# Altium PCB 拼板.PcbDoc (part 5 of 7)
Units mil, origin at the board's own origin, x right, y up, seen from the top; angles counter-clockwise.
Board outline 3630.03 x 5330.03 mil, 2 copper layers (Top Layer, Bottom Layer); 416 components, 35 nets, 1936 pads, 800 vias.
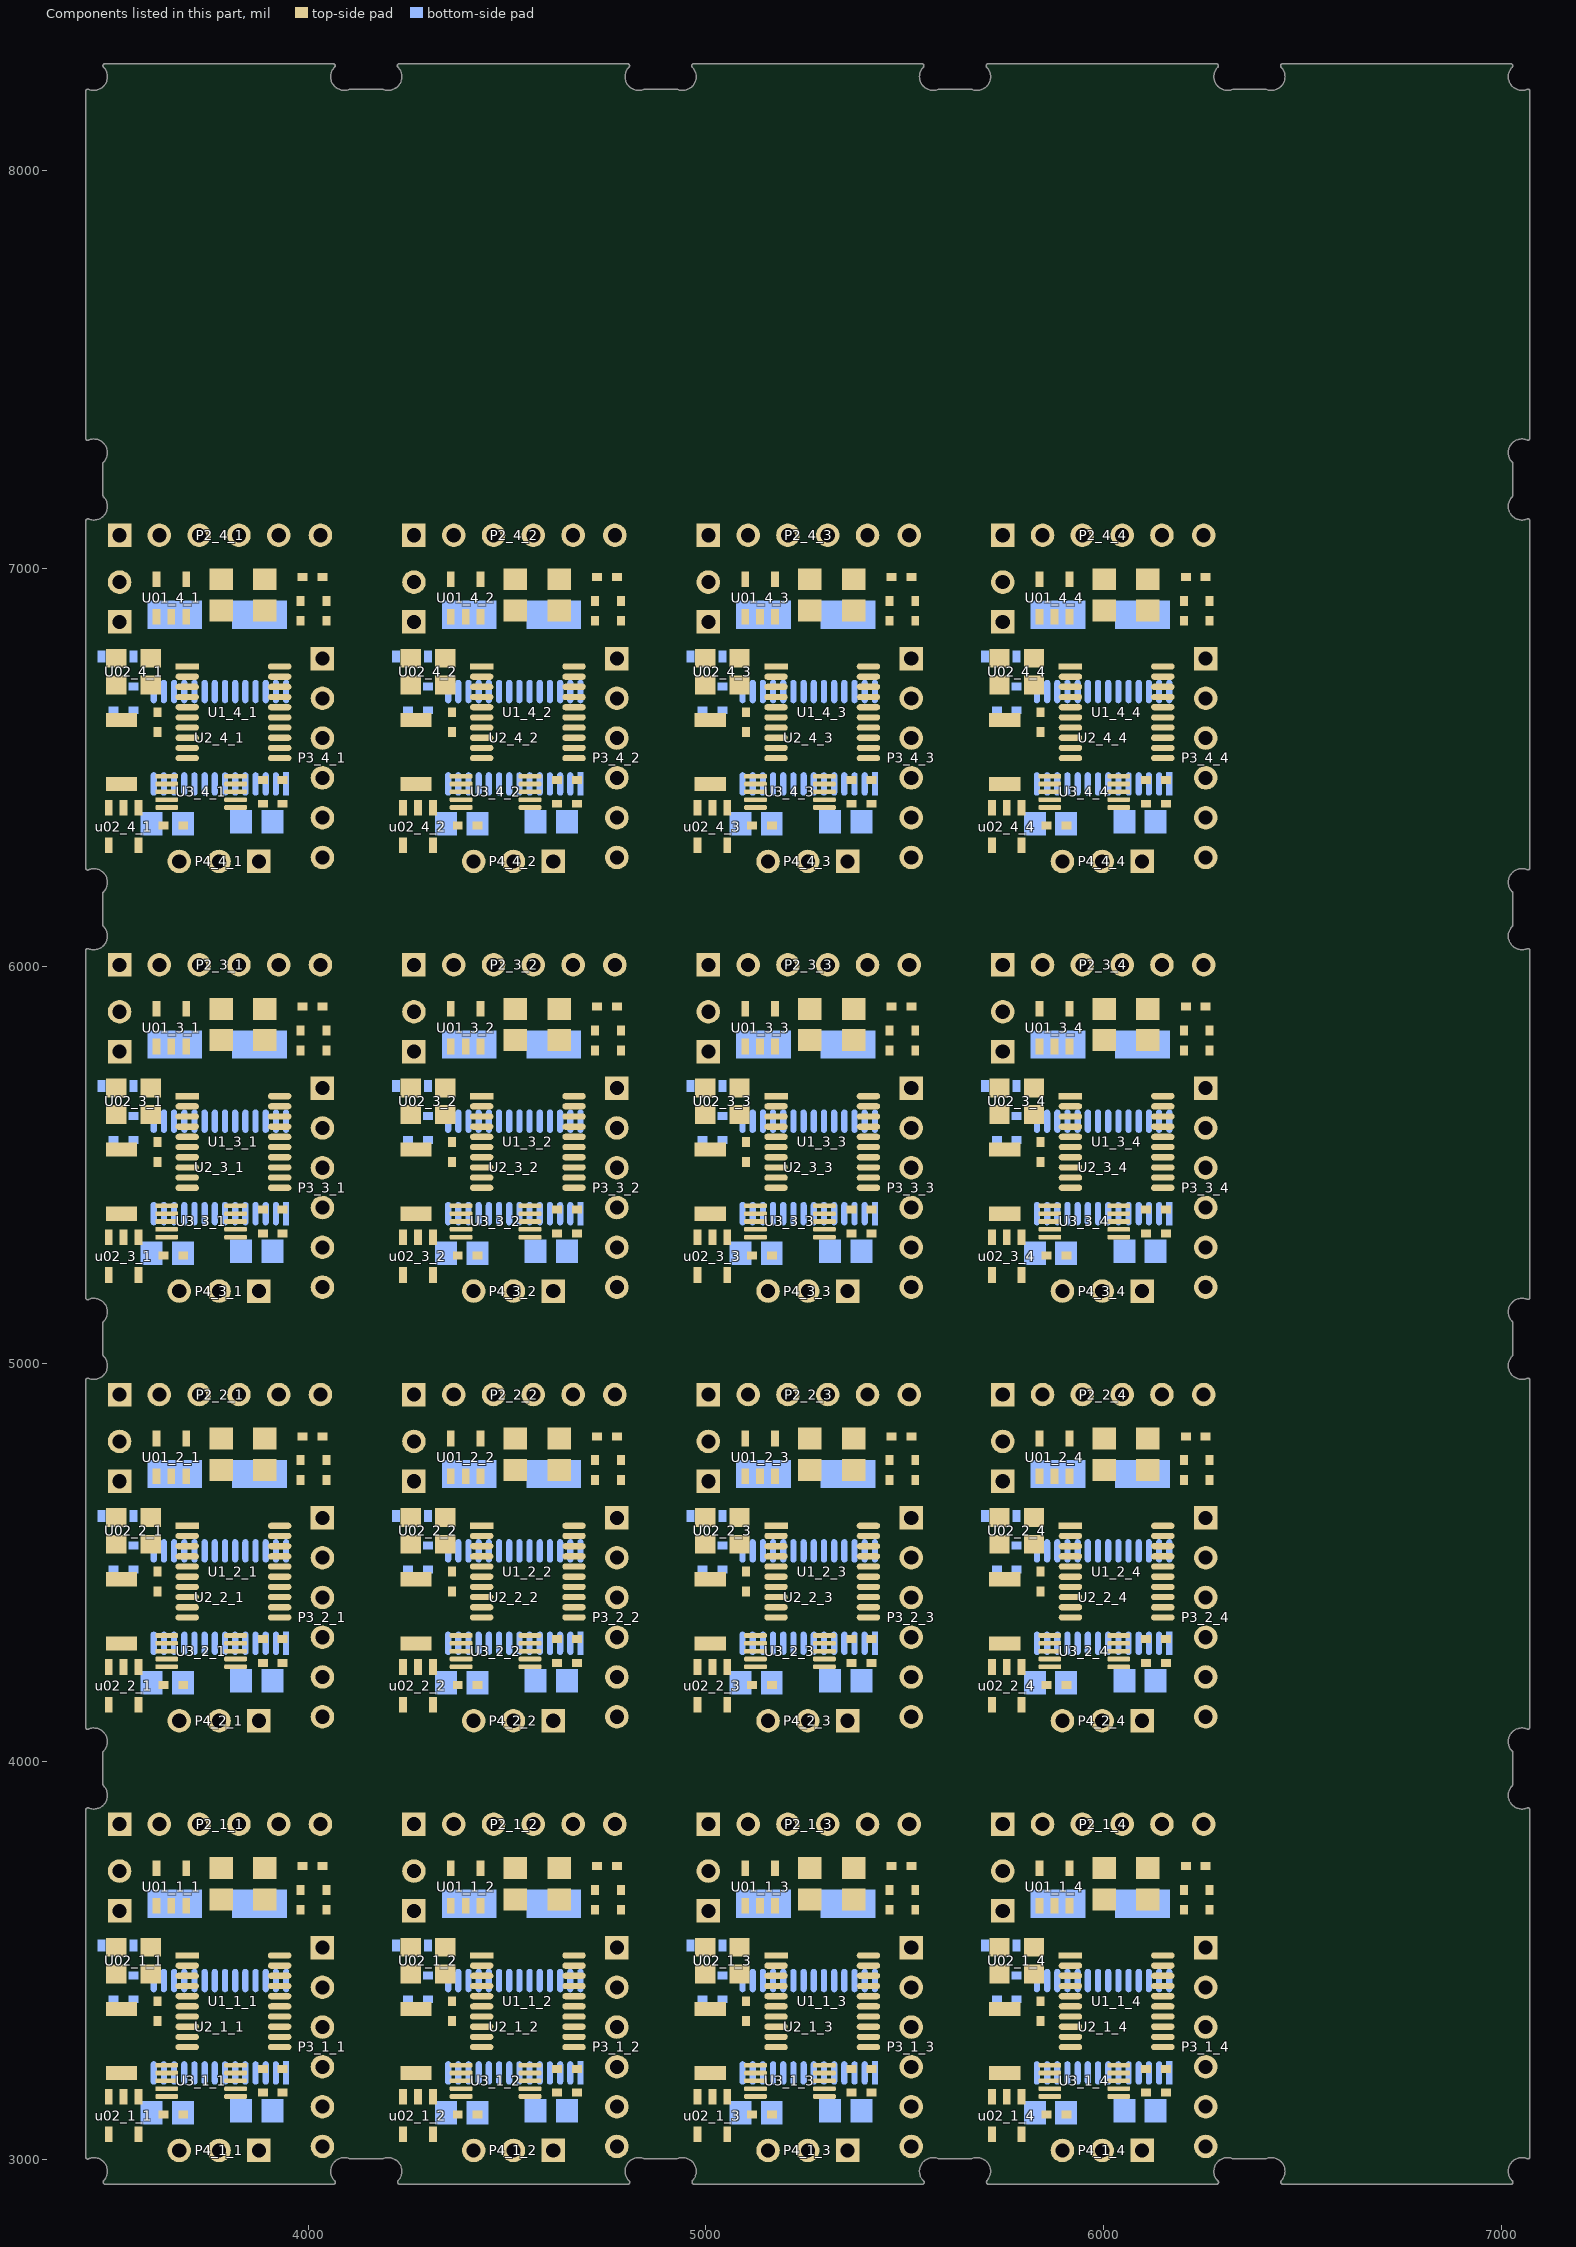
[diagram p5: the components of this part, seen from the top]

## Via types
v1: diameter 24, hole 24, Top Layer to Bottom Layer, 480 vias
v2: diameter 20, hole 10, Top Layer to Bottom Layer, 240 vias
v3: diameter 36, hole 20, Top Layer to Bottom Layer, 48 vias
v4: diameter 32, hole 16, Top Layer to Bottom Layer, 32 vias

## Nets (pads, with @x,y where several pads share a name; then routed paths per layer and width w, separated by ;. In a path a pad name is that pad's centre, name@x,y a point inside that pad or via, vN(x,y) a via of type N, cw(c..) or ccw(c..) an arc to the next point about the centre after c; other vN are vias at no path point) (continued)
copper on no net: (continued)
  Bottom Layer w8: 3511.07,3403.02 3513.57,3403.02 3519.57,3409.02 3519.57,3424.02 3558.57,3463.02 3561.07,3463.02 3608.35,3463.02 3611.93,3459.44 3611.93,3450.02 ; 3511.07,4483.02 3513.57,4483.02 3519.57,4489.02 3519.57,4504.02 3558.57,4543.02 3561.07,4543.02 3608.35,4543.02 3611.93,4539.44 3611.93,4530.02 ; 3511.07,5563.02 3513.57,5563.02 3519.57,5569.02 3519.57,5584.02 3558.57,5623.02 3561.07,5623.02 3608.35,5623.02 3611.93,5619.44 3611.93,5610.02 ; 3511.07,6643.02 3513.57,6643.02 3519.57,6649.02 3519.57,6664.02 3558.57,6703.02 3561.07,6703.02 3608.35,6703.02 3611.93,6699.44 3611.93,6690.02 ; 3561.07,3403.02 3608.18,3403.02 3723.18,3288.02 v2(3756.07,3288.02) 3756.07,3318.02 3688.7,3385.38 3688.7,3450.02 ; 3561.07,4483.02 3608.18,4483.02 3723.18,4368.02 v2(3756.07,4368.02) 3756.07,4398.02 3688.7,4465.38 3688.7,4530.02 ; 3561.07,5563.02 3608.18,5563.02 3723.18,5448.02 v2(3756.07,5448.02) 3756.07,5478.02 3688.7,5545.38 3688.7,5610.02 ; 3561.07,6643.02 3608.18,6643.02 3723.18,6528.02 v2(3756.07,6528.02) 3756.07,6558.02 3688.7,6625.38 3688.7,6690.02 ; 3611.93,3460.85 3611.93,3473.77 ; 3611.93,4540.85 3611.93,4553.77 ; 3611.93,5620.85 3611.93,5633.77 ; 3611.93,6700.85 3611.93,6713.77 ; 3626.07,3843.02 3751.07,3718.02 3751.07,3549.68 v2(3752.72,3548.02) ; 3626.07,4923.02 3751.07,4798.02 3751.07,4629.68 v2(3752.72,4628.02) ; 3626.07,6003.02 3751.07,5878.02 3751.07,5709.68 v2(3752.72,5708.02) ; 3626.07,7083.02 3751.07,6958.02 3751.07,6789.68 v2(3752.72,6788.02) ; 3663.11,3450.02 3663.11,3380.98 v2(3736.07,3308.02) ; 3663.11,4530.02 3663.11,4460.98 v2(3736.07,4388.02) ; 3663.11,5610.02 3663.11,5540.98 v2(3736.07,5468.02) ; 3663.11,6690.02 3663.11,6620.98 v2(3736.07,6548.02) ; 3726.07,3843.02 3764.07,3805.02 3764.07,3590.02 v2(3806.07,3548.02) ; 3726.07,4923.02 3764.07,4885.02 3764.07,4670.02 v2(3806.07,4628.02) ; 3726.07,6003.02 3764.07,5965.02 3764.07,5750.02 v2(3806.07,5708.02) ; 3726.07,7083.02 3764.07,7045.02 3764.07,6830.02 v2(3806.07,6788.02) ; v2(3771.48,3341.51) 3771.48,3315.74 3789.2,3298.02 3932.84,3298.02 3957.84,3273.02 3991.07,3239.8 3991.07,3178.02 4036.07,3133.02 ; v2(3771.48,4421.51) 3771.48,4395.74 3789.2,4378.02 3932.84,4378.02 3957.84,4353.02 3991.07,4319.8 3991.07,4258.02 4036.07,4213.02 ; v2(3771.48,5501.51) 3771.48,5475.74 3789.2,5458.02 3932.84,5458.02 3957.84,5433.02 3991.07,5399.8 3991.07,5338.02 4036.07,5293.02 ; v2(3771.48,6581.51) 3771.48,6555.74 3789.2,6538.02 3932.84,6538.02 3957.84,6513.02 3991.07,6479.8 3991.07,6418.02 4036.07,6373.02 ; v2(3796.07,3322.51) 3946.58,3322.51 4036.07,3233.02 ; v2(3796.07,4402.51) 3946.58,4402.51 4036.07,4313.02 ; v2(3796.07,5482.51) 3946.58,5482.51 4036.07,5393.02 ; v2(3796.07,6562.51) 3946.58,6562.51 4036.07,6473.02 ; v2(3816.07,3413.02) 3816.07,3433.02 ; v2(3816.07,4493.02) 3816.07,4513.02 ; v2(3816.07,5573.02) 3816.07,5593.02 ; v2(3816.07,6653.02) 3816.07,6673.02 ; 3816.66,3450.02 3816.07,3449.43 3816.07,3433.02 ; 3816.66,4530.02 3816.07,4529.43 3816.07,4513.02 ; 3816.66,5610.02 3816.07,5609.43 3816.07,5593.02 ; 3816.66,6690.02 3816.07,6689.43 3816.07,6673.02 ; 3821.07,3438.02 3816.07,3433.02 ; 3821.07,4518.02 3816.07,4513.02 ; 3821.07,5598.02 3816.07,5593.02 ; 3821.07,6678.02 3816.07,6673.02 ; 3826.07,3843.02 3778.07,3795.02 3778.07,3606.88 v2(3836.92,3548.02) ; 3826.07,4923.02 3778.07,4875.02 3778.07,4686.88 v2(3836.92,4628.02) ; 3826.07,6003.02 3778.07,5955.02 3778.07,5766.88 v2(3836.92,5708.02) ; 3826.07,7083.02 3778.07,7035.02 3778.07,6846.88 v2(3836.92,6788.02) ; v2(3836.07,3373.02) 3837.57,3371.52 3878.96,3371.52 3919.02,3411.58 3919.02,3450.02 ; v2(3836.07,4453.02) 3837.57,4451.52 3878.96,4451.52 3919.02,4491.58 3919.02,4530.02 ; v2(3836.07,5533.02) 3837.57,5531.52 3878.96,5531.52 3919.02,5571.58 3919.02,5610.02 ; v2(3836.07,6613.02) 3837.57,6611.52 3878.96,6611.52 3919.02,6651.58 3919.02,6690.02 ; v2(3866.07,3390.52) 3866.07,3448.25 3867.84,3450.02 ; v2(3866.07,3548.02) 3825.54,3588.55 3814.78,3588.55 3791.07,3612.26 3791.07,3708.02 3926.07,3843.02 ; v2(3866.07,4470.52) 3866.07,4528.25 3867.84,4530.02 ; v2(3866.07,4628.02) 3825.54,4668.55 3814.78,4668.55 3791.07,4692.26 3791.07,4788.02 3926.07,4923.02 ; v2(3866.07,5550.52) 3866.07,5608.25 3867.84,5610.02 ; v2(3866.07,5708.02) 3825.54,5748.55 3814.78,5748.55 3791.07,5772.26 3791.07,5868.02 3926.07,6003.02 ; v2(3866.07,6630.52) 3866.07,6688.25 3867.84,6690.02 ; v2(3866.07,6788.02) 3825.54,6828.55 3814.78,6828.55 3791.07,6852.26 3791.07,6948.02 3926.07,7083.02 ; 3893.43,3217.74 3893.43,3239.39 3910.3,3256.27 3956.21,3256.27 3976.07,3236.41 v2(3976.07,3138.02) ; 3893.43,4297.74 3893.43,4319.39 3910.3,4336.27 3956.21,4336.27 3976.07,4316.41 v2(3976.07,4218.02) ; 3893.43,5377.74 3893.43,5399.39 3910.3,5416.27 3956.21,5416.27 3976.07,5396.41 v2(3976.07,5298.02) ; 3893.43,6457.74 3893.43,6479.39 3910.3,6496.27 3956.21,6496.27 3976.07,6476.41 v2(3976.07,6378.02) ; 4251.07,3403.02 4253.57,3403.02 4259.57,3409.02 4259.57,3424.02 4298.57,3463.02 4301.07,3463.02 4348.35,3463.02 4351.93,3459.44 4351.93,3450.02 ; 4251.07,4483.02 4253.57,4483.02 4259.57,4489.02 4259.57,4504.02 4298.57,4543.02 4301.07,4543.02 4348.35,4543.02 4351.93,4539.44 4351.93,4530.02 ; 4251.07,5563.02 4253.57,5563.02 4259.57,5569.02 4259.57,5584.02 4298.57,5623.02 4301.07,5623.02 4348.35,5623.02 4351.93,5619.44 4351.93,5610.02 ; 4251.07,6643.02 4253.57,6643.02 4259.57,6649.02 4259.57,6664.02 4298.57,6703.02 4301.07,6703.02 4348.35,6703.02 4351.93,6699.44 4351.93,6690.02 ; 4301.07,3403.02 4348.18,3403.02 4463.18,3288.02 v2(4496.07,3288.02) 4496.07,3318.02 4428.7,3385.38 4428.7,3450.02 ; 4301.07,4483.02 4348.18,4483.02 4463.18,4368.02 v2(4496.07,4368.02) 4496.07,4398.02 4428.7,4465.38 4428.7,4530.02 ; 4301.07,5563.02 4348.18,5563.02 4463.18,5448.02 v2(4496.07,5448.02) 4496.07,5478.02 4428.7,5545.38 4428.7,5610.02 ; 4301.07,6643.02 4348.18,6643.02 4463.18,6528.02 v2(4496.07,6528.02) 4496.07,6558.02 4428.7,6625.38 4428.7,6690.02 ; 4351.93,3460.85 4351.93,3473.77 ; 4351.93,4540.85 4351.93,4553.77 ; 4351.93,5620.85 4351.93,5633.77 ; 4351.93,6700.85 4351.93,6713.77 ; 4366.07,3843.02 4491.07,3718.02 4491.07,3549.68 v2(4492.72,3548.02) ; 4366.07,4923.02 4491.07,4798.02 4491.07,4629.68 v2(4492.72,4628.02) ; 4366.07,6003.02 4491.07,5878.02 4491.07,5709.68 v2(4492.72,5708.02) ; 4366.07,7083.02 4491.07,6958.02 4491.07,6789.68 v2(4492.72,6788.02) ; 4403.11,3450.02 4403.11,3380.98 v2(4476.07,3308.02) ; 4403.11,4530.02 4403.11,4460.98 v2(4476.07,4388.02) ; 4403.11,5610.02 4403.11,5540.98 v2(4476.07,5468.02) ; 4403.11,6690.02 4403.11,6620.98 v2(4476.07,6548.02) ; 4466.07,3843.02 4504.07,3805.02 4504.07,3590.02 v2(4546.07,3548.02) ; 4466.07,4923.02 4504.07,4885.02 4504.07,4670.02 v2(4546.07,4628.02) ; 4466.07,6003.02 4504.07,5965.02 4504.07,5750.02 v2(4546.07,5708.02) ; 4466.07,7083.02 4504.07,7045.02 4504.07,6830.02 v2(4546.07,6788.02) ; v2(4511.48,3341.51) 4511.48,3315.74 4529.2,3298.02 4672.84,3298.02 4697.84,3273.02 4731.07,3239.8 4731.07,3178.02 4776.07,3133.02 ; v2(4511.48,4421.51) 4511.48,4395.74 4529.2,4378.02 4672.84,4378.02 4697.84,4353.02 4731.07,4319.8 4731.07,4258.02 4776.07,4213.02 ; v2(4511.48,5501.51) 4511.48,5475.74 4529.2,5458.02 4672.84,5458.02 4697.84,5433.02 4731.07,5399.8 4731.07,5338.02 4776.07,5293.02 ; v2(4511.48,6581.51) 4511.48,6555.74 4529.2,6538.02 4672.84,6538.02 4697.84,6513.02 4731.07,6479.8 4731.07,6418.02 4776.07,6373.02 ; v2(4536.07,3322.51) 4686.58,3322.51 4776.07,3233.02 ; v2(4536.07,4402.51) 4686.58,4402.51 4776.07,4313.02 ; v2(4536.07,5482.51) 4686.58,5482.51 4776.07,5393.02 ; v2(4536.07,6562.51) 4686.58,6562.51 4776.07,6473.02 ; v2(4556.07,3413.02) 4556.07,3433.02 ; v2(4556.07,4493.02) 4556.07,4513.02 ; v2(4556.07,5573.02) 4556.07,5593.02 ; v2(4556.07,6653.02) 4556.07,6673.02 ; 4556.66,3450.02 4556.07,3449.43 4556.07,3433.02 ; 4556.66,4530.02 4556.07,4529.43 4556.07,4513.02 ; 4556.66,5610.02 4556.07,5609.43 4556.07,5593.02 ; 4556.66,6690.02 4556.07,6689.43 4556.07,6673.02 ; 4561.07,3438.02 4556.07,3433.02 ; 4561.07,4518.02 4556.07,4513.02 ; 4561.07,5598.02 4556.07,5593.02 ; 4561.07,6678.02 4556.07,6673.02 ; 4566.07,3843.02 4518.07,3795.02 4518.07,3606.88 v2(4576.92,3548.02) ; 4566.07,4923.02 4518.07,4875.02 4518.07,4686.88 v2(4576.92,4628.02) ; 4566.07,6003.02 4518.07,5955.02 4518.07,5766.88 v2(4576.92,5708.02) ; 4566.07,7083.02 4518.07,7035.02 4518.07,6846.88 v2(4576.92,6788.02) ; v2(4576.07,3373.02) 4577.57,3371.52 4618.96,3371.52 4659.02,3411.58 4659.02,3450.02 ; v2(4576.07,4453.02) 4577.57,4451.52 4618.96,4451.52 4659.02,4491.58 4659.02,4530.02 ; v2(4576.07,5533.02) 4577.57,5531.52 4618.96,5531.52 4659.02,5571.58 4659.02,5610.02 ; v2(4576.07,6613.02) 4577.57,6611.52 4618.96,6611.52 4659.02,6651.58 4659.02,6690.02 ; v2(4606.07,3390.52) 4606.07,3448.25 4607.84,3450.02 ; v2(4606.07,3548.02) 4565.54,3588.55 4554.78,3588.55 4531.07,3612.26 4531.07,3708.02 4666.07,3843.02 ; v2(4606.07,4470.52) 4606.07,4528.25 4607.84,4530.02 ; v2(4606.07,4628.02) 4565.54,4668.55 4554.78,4668.55 4531.07,4692.26 4531.07,4788.02 4666.07,4923.02 ; v2(4606.07,5550.52) 4606.07,5608.25 4607.84,5610.02 ; v2(4606.07,5708.02) 4565.54,5748.55 4554.78,5748.55 4531.07,5772.26 4531.07,5868.02 4666.07,6003.02 ; v2(4606.07,6630.52) 4606.07,6688.25 4607.84,6690.02 ; v2(4606.07,6788.02) 4565.54,6828.55 4554.78,6828.55 4531.07,6852.26 4531.07,6948.02 4666.07,7083.02 ; 4633.43,3217.74 4633.43,3239.39 4650.3,3256.27 4696.21,3256.27 4716.07,3236.41 v2(4716.07,3138.02) ; 4633.43,4297.74 4633.43,4319.39 4650.3,4336.27 4696.21,4336.27 4716.07,4316.41 v2(4716.07,4218.02) ; 4633.43,5377.74 4633.43,5399.39 4650.3,5416.27 4696.21,5416.27 4716.07,5396.41 v2(4716.07,5298.02) ; 4633.43,6457.74 4633.43,6479.39 4650.3,6496.27 4696.21,6496.27 4716.07,6476.41 v2(4716.07,6378.02) ; 4991.07,3403.02 4993.57,3403.02 4999.57,3409.02 4999.57,3424.02 5038.57,3463.02 5041.07,3463.02 5088.35,3463.02 5091.93,3459.44 5091.93,3450.02 ; 4991.07,4483.02 4993.57,4483.02 4999.57,4489.02 4999.57,4504.02 5038.57,4543.02 5041.07,4543.02 5088.35,4543.02 5091.93,4539.44 5091.93,4530.02 ; 4991.07,5563.02 4993.57,5563.02 4999.57,5569.02 4999.57,5584.02 5038.57,5623.02 5041.07,5623.02 5088.35,5623.02 5091.93,5619.44 5091.93,5610.02 ; 4991.07,6643.02 4993.57,6643.02 4999.57,6649.02 4999.57,6664.02 5038.57,6703.02 5041.07,6703.02 5088.35,6703.02 5091.93,6699.44 5091.93,6690.02 ; 5041.07,3403.02 5088.18,3403.02 5203.18,3288.02 v2(5236.07,3288.02) 5236.07,3318.02 5168.7,3385.38 5168.7,3450.02 ; 5041.07,4483.02 5088.18,4483.02 5203.18,4368.02 v2(5236.07,4368.02) 5236.07,4398.02 5168.7,4465.38 5168.7,4530.02 ; 5041.07,5563.02 5088.18,5563.02 5203.18,5448.02 v2(5236.07,5448.02) 5236.07,5478.02 5168.7,5545.38 5168.7,5610.02 ; 5041.07,6643.02 5088.18,6643.02 5203.18,6528.02 v2(5236.07,6528.02) 5236.07,6558.02 5168.7,6625.38 5168.7,6690.02 ; 5091.93,3460.85 5091.93,3473.77 ; 5091.93,4540.85 5091.93,4553.77 ; 5091.93,5620.85 5091.93,5633.77 ; 5091.93,6700.85 5091.93,6713.77 ; 5106.07,3843.02 5231.07,3718.02 5231.07,3549.68 v2(5232.72,3548.02) ; 5106.07,4923.02 5231.07,4798.02 5231.07,4629.68 v2(5232.72,4628.02) ; 5106.07,6003.02 5231.07,5878.02 5231.07,5709.68 v2(5232.72,5708.02) ; 5106.07,7083.02 5231.07,6958.02 5231.07,6789.68 v2(5232.72,6788.02) ; 5143.11,3450.02 5143.11,3380.98 v2(5216.07,3308.02) ; 5143.11,4530.02 5143.11,4460.98 v2(5216.07,4388.02) ; 5143.11,5610.02 5143.11,5540.98 v2(5216.07,5468.02) ; 5143.11,6690.02 5143.11,6620.98 v2(5216.07,6548.02) ; 5206.07,3843.02 5244.07,3805.02 5244.07,3590.02 v2(5286.07,3548.02) ; 5206.07,4923.02 5244.07,4885.02 5244.07,4670.02 v2(5286.07,4628.02) ; 5206.07,6003.02 5244.07,5965.02 5244.07,5750.02 v2(5286.07,5708.02) ; 5206.07,7083.02 5244.07,7045.02 5244.07,6830.02 v2(5286.07,6788.02) ; v2(5251.48,3341.51) 5251.48,3315.74 5269.2,3298.02 5412.84,3298.02 5437.84,3273.02 5471.07,3239.8 5471.07,3178.02 5516.07,3133.02 ; v2(5251.48,4421.51) 5251.48,4395.74 5269.2,4378.02 5412.84,4378.02 5437.84,4353.02 5471.07,4319.8 5471.07,4258.02 5516.07,4213.02 ; v2(5251.48,5501.51) 5251.48,5475.74 5269.2,5458.02 5412.84,5458.02 5437.84,5433.02 5471.07,5399.8 5471.07,5338.02 5516.07,5293.02 ; v2(5251.48,6581.51) 5251.48,6555.74 5269.2,6538.02 5412.84,6538.02 5437.84,6513.02 5471.07,6479.8 5471.07,6418.02 5516.07,6373.02 ; v2(5276.07,3322.51) 5426.58,3322.51 5516.07,3233.02 ; v2(5276.07,4402.51) 5426.58,4402.51 5516.07,4313.02 ; v2(5276.07,5482.51) 5426.58,5482.51 5516.07,5393.02 ; v2(5276.07,6562.51) 5426.58,6562.51 5516.07,6473.02 ; v2(5296.07,3413.02) 5296.07,3433.02 ; v2(5296.07,4493.02) 5296.07,4513.02 ; v2(5296.07,5573.02) 5296.07,5593.02 ; v2(5296.07,6653.02) 5296.07,6673.02 ; 5296.66,3450.02 5296.07,3449.43 5296.07,3433.02 ; 5296.66,4530.02 5296.07,4529.43 5296.07,4513.02 ; 5296.66,5610.02 5296.07,5609.43 5296.07,5593.02 ; 5296.66,6690.02 5296.07,6689.43 5296.07,6673.02 ; 5301.07,3438.02 5296.07,3433.02 ; 5301.07,4518.02 5296.07,4513.02 ; 5301.07,5598.02 5296.07,5593.02 ; 5301.07,6678.02 5296.07,6673.02 ; 5306.07,3843.02 5258.07,3795.02 5258.07,3606.88 v2(5316.92,3548.02) ; 5306.07,4923.02 5258.07,4875.02 5258.07,4686.88 v2(5316.92,4628.02) ; 5306.07,6003.02 5258.07,5955.02 5258.07,5766.88 v2(5316.92,5708.02) ; 5306.07,7083.02 5258.07,7035.02 5258.07,6846.88 v2(5316.92,6788.02) ; v2(5316.07,3373.02) 5317.57,3371.52 5358.96,3371.52 5399.02,3411.58 5399.02,3450.02 ; v2(5316.07,4453.02) 5317.57,4451.52 5358.96,4451.52 5399.02,4491.58 5399.02,4530.02 ; v2(5316.07,5533.02) 5317.57,5531.52 5358.96,5531.52 5399.02,5571.58 5399.02,5610.02 ; v2(5316.07,6613.02) 5317.57,6611.52 5358.96,6611.52 5399.02,6651.58 5399.02,6690.02 ; v2(5346.07,3390.52) 5346.07,3448.25 5347.84,3450.02 ; v2(5346.07,3548.02) 5305.54,3588.55 5294.78,3588.55 5271.07,3612.26 5271.07,3708.02 5406.07,3843.02 ; v2(5346.07,4470.52) 5346.07,4528.25 5347.84,4530.02 ; v2(5346.07,4628.02) 5305.54,4668.55 5294.78,4668.55 5271.07,4692.26 5271.07,4788.02 5406.07,4923.02 ; v2(5346.07,5550.52) 5346.07,5608.25 5347.84,5610.02 ; v2(5346.07,5708.02) 5305.54,5748.55 5294.78,5748.55 5271.07,5772.26 5271.07,5868.02 5406.07,6003.02 ; v2(5346.07,6630.52) 5346.07,6688.25 5347.84,6690.02 ; v2(5346.07,6788.02) 5305.54,6828.55 5294.78,6828.55 5271.07,6852.26 5271.07,6948.02 5406.07,7083.02 ; 5373.43,3217.74 5373.43,3239.39 5390.3,3256.27 5436.21,3256.27 5456.07,3236.41 v2(5456.07,3138.02) ; 5373.43,4297.74 5373.43,4319.39 5390.3,4336.27 5436.21,4336.27 5456.07,4316.41 v2(5456.07,4218.02) ; 5373.43,5377.74 5373.43,5399.39 5390.3,5416.27 5436.21,5416.27 5456.07,5396.41 v2(5456.07,5298.02) ; 5373.43,6457.74 5373.43,6479.39 5390.3,6496.27 5436.21,6496.27 5456.07,6476.41 v2(5456.07,6378.02) ; 5731.07,3403.02 5733.57,3403.02 5739.57,3409.02 5739.57,3424.02 5778.57,3463.02 5781.07,3463.02 5828.35,3463.02 5831.93,3459.44 5831.93,3450.02 ; 5731.07,4483.02 5733.57,4483.02 5739.57,4489.02 5739.57,4504.02 5778.57,4543.02 5781.07,4543.02 5828.35,4543.02 5831.93,4539.44 5831.93,4530.02 ; 5731.07,5563.02 5733.57,5563.02 5739.57,5569.02 5739.57,5584.02 5778.57,5623.02 5781.07,5623.02 5828.35,5623.02 5831.93,5619.44 5831.93,5610.02 ; 5731.07,6643.02 5733.57,6643.02 5739.57,6649.02 5739.57,6664.02 5778.57,6703.02 5781.07,6703.02 5828.35,6703.02 5831.93,6699.44 5831.93,6690.02 ; 5781.07,3403.02 5828.18,3403.02 5943.18,3288.02 v2(5976.07,3288.02) 5976.07,3318.02 5908.7,3385.38 5908.7,3450.02 ; 5781.07,4483.02 5828.18,4483.02 5943.18,4368.02 v2(5976.07,4368.02) 5976.07,4398.02 5908.7,4465.38 5908.7,4530.02 ; 5781.07,5563.02 5828.18,5563.02 5943.18,5448.02 v2(5976.07,5448.02) 5976.07,5478.02 5908.7,5545.38 5908.7,5610.02 ; 5781.07,6643.02 5828.18,6643.02 5943.18,6528.02 v2(5976.07,6528.02) 5976.07,6558.02 5908.7,6625.38 5908.7,6690.02 ; 5831.93,3460.85 5831.93,3473.77 ; 5831.93,4540.85 5831.93,4553.77 ; 5831.93,5620.85 5831.93,5633.77 ; 5831.93,6700.85 5831.93,6713.77 ; 5846.07,3843.02 5971.07,3718.02 5971.07,3549.68 v2(5972.72,3548.02) ; 5846.07,4923.02 5971.07,4798.02 5971.07,4629.68 v2(5972.72,4628.02) ; 5846.07,6003.02 5971.07,5878.02 5971.07,5709.68 v2(5972.72,5708.02) ; 5846.07,7083.02 5971.07,6958.02 5971.07,6789.68 v2(5972.72,6788.02) ; 5883.11,3450.02 5883.11,3380.98 v2(5956.07,3308.02) ; 5883.11,4530.02 5883.11,4460.98 v2(5956.07,4388.02) ; 5883.11,5610.02 5883.11,5540.98 v2(5956.07,5468.02) ; 5883.11,6690.02 5883.11,6620.98 v2(5956.07,6548.02) ; 5946.07,3843.02 5984.07,3805.02 5984.07,3590.02 v2(6026.07,3548.02) ; 5946.07,4923.02 5984.07,4885.02 5984.07,4670.02 v2(6026.07,4628.02) ; 5946.07,6003.02 5984.07,5965.02 5984.07,5750.02 v2(6026.07,5708.02) ; 5946.07,7083.02 5984.07,7045.02 5984.07,6830.02 v2(6026.07,6788.02) ; v2(5991.48,3341.51) 5991.48,3315.74 6009.2,3298.02 6152.84,3298.02 6177.84,3273.02 6211.07,3239.8 6211.07,3178.02 6256.07,3133.02 ; v2(5991.48,4421.51) 5991.48,4395.74 6009.2,4378.02 6152.84,4378.02 6177.84,4353.02 6211.07,4319.8 6211.07,4258.02 6256.07,4213.02 ; v2(5991.48,5501.51) 5991.48,5475.74 6009.2,5458.02 6152.84,5458.02 6177.84,5433.02 6211.07,5399.8 6211.07,5338.02 6256.07,5293.02 ; v2(5991.48,6581.51) 5991.48,6555.74 6009.2,6538.02 6152.84,6538.02 6177.84,6513.02 6211.07,6479.8 6211.07,6418.02 6256.07,6373.02 ; v2(6016.07,3322.51) 6166.58,3322.51 6256.07,3233.02 ; v2(6016.07,4402.51) 6166.58,4402.51 6256.07,4313.02 ; v2(6016.07,5482.51) 6166.58,5482.51 6256.07,5393.02 ; v2(6016.07,6562.51) 6166.58,6562.51 6256.07,6473.02 ; v2(6036.07,3413.02) 6036.07,3433.02 ; v2(6036.07,4493.02) 6036.07,4513.02 ; v2(6036.07,5573.02) 6036.07,5593.02 ; v2(6036.07,6653.02) 6036.07,6673.02 ; 6036.66,3450.02 6036.07,3449.43 6036.07,3433.02 ; 6036.66,4530.02 6036.07,4529.43 6036.07,4513.02 ; 6036.66,5610.02 6036.07,5609.43 6036.07,5593.02 ; 6036.66,6690.02 6036.07,6689.43 6036.07,6673.02 ; 6041.07,3438.02 6036.07,3433.02 ; 6041.07,4518.02 6036.07,4513.02 ; 6041.07,5598.02 6036.07,5593.02 ; 6041.07,6678.02 6036.07,6673.02 ; 6046.07,3843.02 5998.07,3795.02 5998.07,3606.88 v2(6056.92,3548.02) ; 6046.07,4923.02 5998.07,4875.02 5998.07,4686.88 v2(6056.92,4628.02) ; 6046.07,6003.02 5998.07,5955.02 5998.07,5766.88 v2(6056.92,5708.02) ; 6046.07,7083.02 5998.07,7035.02 5998.07,6846.88 v2(6056.92,6788.02) ; v2(6056.07,3373.02) 6057.57,3371.52 6098.96,3371.52 6139.02,3411.58 6139.02,3450.02 ; v2(6056.07,4453.02) 6057.57,4451.52 6098.96,4451.52 6139.02,4491.58 6139.02,4530.02 ; v2(6056.07,5533.02) 6057.57,5531.52 6098.96,5531.52 6139.02,5571.58 6139.02,5610.02 ; v2(6056.07,6613.02) 6057.57,6611.52 6098.96,6611.52 6139.02,6651.58 6139.02,6690.02 ; v2(6086.07,3390.52) 6086.07,3448.25 6087.84,3450.02 ; v2(6086.07,3548.02) 6045.54,3588.55 6034.78,3588.55 6011.07,3612.26 6011.07,3708.02 6146.07,3843.02 ; v2(6086.07,4470.52) 6086.07,4528.25 6087.84,4530.02 ; v2(6086.07,4628.02) 6045.54,4668.55 6034.78,4668.55 6011.07,4692.26 6011.07,4788.02 6146.07,4923.02 ; v2(6086.07,5550.52) 6086.07,5608.25 6087.84,5610.02 ; v2(6086.07,5708.02) 6045.54,5748.55 6034.78,5748.55 6011.07,5772.26 6011.07,5868.02 6146.07,6003.02 ; v2(6086.07,6630.52) 6086.07,6688.25 6087.84,6690.02 ; v2(6086.07,6788.02) 6045.54,6828.55 6034.78,6828.55 6011.07,6852.26 6011.07,6948.02 6146.07,7083.02 ; 6113.43,3217.74 6113.43,3239.39 6130.3,3256.27 6176.21,3256.27 6196.07,3236.41 v2(6196.07,3138.02) ; 6113.43,4297.74 6113.43,4319.39 6130.3,4336.27 6176.21,4336.27 6196.07,4316.41 v2(6196.07,4218.02) ; 6113.43,5377.74 6113.43,5399.39 6130.3,5416.27 6176.21,5416.27 6196.07,5396.41 v2(6196.07,5298.02) ; 6113.43,6457.74 6113.43,6479.39 6130.3,6496.27 6176.21,6496.27 6196.07,6476.41 v2(6196.07,6378.02)
  Bottom Layer w16: 3637.52,3450.02 3637.52,3483.18 3646.9,3492.55 v2@3786.07,3492.55 ; 3637.52,4530.02 3637.52,4563.18 3646.9,4572.55 v2@3786.07,4572.55 ; 3637.52,5610.02 3637.52,5643.18 3646.9,5652.55 v2@3786.07,5652.55 ; 3637.52,6690.02 3637.52,6723.18 3646.9,6732.55 v2@3786.07,6732.55 ; 3676.07,3023.02 3742.77,3089.72 3742.77,3188.57 3740.01,3191.33 3740.01,3196.21 ; 3676.07,4103.02 3742.77,4169.72 3742.77,4268.57 3740.01,4271.33 3740.01,4276.21 ; 3676.07,5183.02 3742.77,5249.72 3742.77,5348.57 3740.01,5351.33 3740.01,5356.21 ; 3676.07,6263.02 3742.77,6329.72 3742.77,6428.57 3740.01,6431.33 3740.01,6436.21 ; 3685.44,3118.02 3705,3137.58 3705,3163.45 3713.77,3172.23 v4(3713.77,3176.56) ; 3685.44,4198.02 3705,4217.58 3705,4243.45 3713.77,4252.23 v4(3713.77,4256.56) ; 3685.44,5278.02 3705,5297.58 3705,5323.45 3713.77,5332.23 v4(3713.77,5336.56) ; 3685.44,6358.02 3705,6377.58 3705,6403.45 3713.77,6412.23 v4(3713.77,6416.56) ; v4@3714.17,3171.4 3714.17,3217.61 3714.29,3217.74 ; v4@3714.17,4251.4 3714.17,4297.61 3714.29,4297.74 ; v4@3714.17,5331.4 3714.17,5377.61 3714.29,5377.74 ; v4@3714.17,6411.4 3714.17,6457.61 3714.29,6457.74 ; 3765.48,3217.74 3765.48,3196.34 3766.07,3195.75 3766.07,3053.92 3767.83,3052.16 3767.83,3031.26 3776.07,3023.02 ; 3765.48,4297.74 3765.48,4276.34 3766.07,4275.75 3766.07,4133.92 3767.83,4132.16 3767.83,4111.26 3776.07,4103.02 ; 3765.48,5377.74 3765.48,5356.34 3766.07,5355.75 3766.07,5213.92 3767.83,5212.16 3767.83,5191.26 3776.07,5183.02 ; 3765.48,6457.74 3765.48,6436.34 3766.07,6435.75 3766.07,6293.92 3767.83,6292.16 3767.83,6271.26 3776.07,6263.02 ; v2(3786.07,3498.02) 3787.15,3498.02 3792.81,3492.36 3807.82,3492.36 3808.01,3492.55 3836.07,3492.55 ; v2(3786.07,4578.02) 3787.15,4578.02 3792.81,4572.36 3807.82,4572.36 3808.01,4572.55 3836.07,4572.55 ; v2(3786.07,5658.02) 3787.15,5658.02 3792.81,5652.36 3807.82,5652.36 3808.01,5652.55 3836.07,5652.55 ; v2(3786.07,6738.02) 3787.15,6738.02 3792.81,6732.36 3807.82,6732.36 3808.01,6732.55 3836.07,6732.55 ; 3791.07,3450.02 3791.19,3450.15 3791.19,3483.18 ; 3791.07,4530.02 3791.19,4530.15 3791.19,4563.18 ; 3791.07,5610.02 3791.19,5610.15 3791.19,5643.18 ; 3791.07,6690.02 3791.19,6690.15 3791.19,6723.18 ; 3816.66,3138.06 3816.66,3217.74 ; 3816.66,4218.06 3816.66,4297.74 ; 3816.66,5298.06 3816.66,5377.74 ; 3816.66,6378.06 3816.66,6457.74 ; 3842.25,3196.21 3842.25,3192.16 3868.86,3165.55 3943.38,3165.55 3951,3157.93 3951,3067.95 3927.59,3044.55 3897.59,3044.55 3876.07,3023.02 ; 3842.25,3471.43 3842.25,3450.02 3842.12,3450.15 3842.12,3486.5 3836.07,3492.55 ; 3842.25,4276.21 3842.25,4272.16 3868.86,4245.55 3943.38,4245.55 3951,4237.93 3951,4147.95 3927.59,4124.55 3897.59,4124.55 3876.07,4103.02 ; 3842.25,4551.43 3842.25,4530.02 3842.12,4530.15 3842.12,4566.5 3836.07,4572.55 ; 3842.25,5356.21 3842.25,5352.16 3868.86,5325.55 3943.38,5325.55 3951,5317.93 3951,5227.95 3927.59,5204.55 3897.59,5204.55 3876.07,5183.02 ; 3842.25,5631.43 3842.25,5610.02 3842.12,5610.15 3842.12,5646.5 3836.07,5652.55 ; 3842.25,6436.21 3842.25,6432.16 3868.86,6405.55 3943.38,6405.55 3951,6397.93 3951,6307.95 3927.59,6284.55 3897.59,6284.55 3876.07,6263.02 ; 3842.25,6711.43 3842.25,6690.02 3842.12,6690.15 3842.12,6726.5 3836.07,6732.55 ; 3893.43,3450.02 3893.43,3478.65 3879.53,3492.55 3836.07,3492.55 ; 3893.43,4530.02 3893.43,4558.65 3879.53,4572.55 3836.07,4572.55 ; 3893.43,5610.02 3893.43,5638.65 3879.53,5652.55 3836.07,5652.55 ; 3893.43,6690.02 3893.43,6718.65 3879.53,6732.55 3836.07,6732.55 ; 4377.52,3450.02 4377.52,3483.18 4386.9,3492.55 v2@4526.07,3492.55 ; 4377.52,4530.02 4377.52,4563.18 4386.9,4572.55 v2@4526.07,4572.55 ; 4377.52,5610.02 4377.52,5643.18 4386.9,5652.55 v2@4526.07,5652.55 ; 4377.52,6690.02 4377.52,6723.18 4386.9,6732.55 v2@4526.07,6732.55 ; 4416.07,3023.02 4482.77,3089.72 4482.77,3188.57 4480.01,3191.33 4480.01,3196.21 ; 4416.07,4103.02 4482.77,4169.72 4482.77,4268.57 4480.01,4271.33 4480.01,4276.21 ; 4416.07,5183.02 4482.77,5249.72 4482.77,5348.57 4480.01,5351.33 4480.01,5356.21 ; 4416.07,6263.02 4482.77,6329.72 4482.77,6428.57 4480.01,6431.33 4480.01,6436.21 ; 4425.44,3118.02 4445,3137.58 4445,3163.45 4453.77,3172.23 v4(4453.77,3176.56) ; 4425.44,4198.02 4445,4217.58 4445,4243.45 4453.77,4252.23 v4(4453.77,4256.56) ; 4425.44,5278.02 4445,5297.58 4445,5323.45 4453.77,5332.23 v4(4453.77,5336.56) ; 4425.44,6358.02 4445,6377.58 4445,6403.45 4453.77,6412.23 v4(4453.77,6416.56) ; v4@4454.17,3171.4 4454.17,3217.61 4454.29,3217.74 ; v4@4454.17,4251.4 4454.17,4297.61 4454.29,4297.74 ; v4@4454.17,5331.4 4454.17,5377.61 4454.29,5377.74 ; v4@4454.17,6411.4 4454.17,6457.61 4454.29,6457.74 ; 4505.48,3217.74 4505.48,3196.34 4506.07,3195.75 4506.07,3053.92 4507.83,3052.16 4507.83,3031.26 4516.07,3023.02 ; 4505.48,4297.74 4505.48,4276.34 4506.07,4275.75 4506.07,4133.92 4507.83,4132.16 4507.83,4111.26 4516.07,4103.02 ; 4505.48,5377.74 4505.48,5356.34 4506.07,5355.75 4506.07,5213.92 4507.83,5212.16 4507.83,5191.26 4516.07,5183.02 ; 4505.48,6457.74 4505.48,6436.34 4506.07,6435.75 4506.07,6293.92 4507.83,6292.16 4507.83,6271.26 4516.07,6263.02 ; v2(4526.07,3498.02) 4527.15,3498.02 4532.81,3492.36 4547.82,3492.36 4548.01,3492.55 4576.07,3492.55 ; v2(4526.07,4578.02) 4527.15,4578.02 4532.81,4572.36 4547.82,4572.36 4548.01,4572.55 4576.07,4572.55 ; v2(4526.07,5658.02) 4527.15,5658.02 4532.81,5652.36 4547.82,5652.36 4548.01,5652.55 4576.07,5652.55 ; v2(4526.07,6738.02) 4527.15,6738.02 4532.81,6732.36 4547.82,6732.36 4548.01,6732.55 4576.07,6732.55 ; 4531.07,3450.02 4531.19,3450.15 4531.19,3483.18 ; 4531.07,4530.02 4531.19,4530.15 4531.19,4563.18 ; 4531.07,5610.02 4531.19,5610.15 4531.19,5643.18 ; 4531.07,6690.02 4531.19,6690.15 4531.19,6723.18 ; 4556.66,3138.06 4556.66,3217.74 ; 4556.66,4218.06 4556.66,4297.74 ; 4556.66,5298.06 4556.66,5377.74 ; 4556.66,6378.06 4556.66,6457.74 ; 4582.25,3196.21 4582.25,3192.16 4608.86,3165.55 4683.38,3165.55 4691,3157.93 4691,3067.95 4667.59,3044.55 4637.59,3044.55 4616.07,3023.02 ; 4582.25,3471.43 4582.25,3450.02 4582.12,3450.15 4582.12,3486.5 4576.07,3492.55 ; 4582.25,4276.21 4582.25,4272.16 4608.86,4245.55 4683.38,4245.55 4691,4237.93 4691,4147.95 4667.59,4124.55 4637.59,4124.55 4616.07,4103.02 ; 4582.25,4551.43 4582.25,4530.02 4582.12,4530.15 4582.12,4566.5 4576.07,4572.55 ; 4582.25,5356.21 4582.25,5352.16 4608.86,5325.55 4683.38,5325.55 4691,5317.93 4691,5227.95 4667.59,5204.55 4637.59,5204.55 4616.07,5183.02 ; 4582.25,5631.43 4582.25,5610.02 4582.12,5610.15 4582.12,5646.5 4576.07,5652.55 ; 4582.25,6436.21 4582.25,6432.16 4608.86,6405.55 4683.38,6405.55 4691,6397.93 4691,6307.95 4667.59,6284.55 4637.59,6284.55 4616.07,6263.02 ; 4582.25,6711.43 4582.25,6690.02 4582.12,6690.15 4582.12,6726.5 4576.07,6732.55 ; 4633.43,3450.02 4633.43,3478.65 4619.53,3492.55 4576.07,3492.55 ; 4633.43,4530.02 4633.43,4558.65 4619.53,4572.55 4576.07,4572.55 ; 4633.43,5610.02 4633.43,5638.65 4619.53,5652.55 4576.07,5652.55 ; 4633.43,6690.02 4633.43,6718.65 4619.53,6732.55 4576.07,6732.55 ; 5117.52,3450.02 5117.52,3483.18 5126.9,3492.55 v2@5266.07,3492.55 ; 5117.52,4530.02 5117.52,4563.18 5126.9,4572.55 v2@5266.07,4572.55 ; 5117.52,5610.02 5117.52,5643.18 5126.9,5652.55 v2@5266.07,5652.55 ; 5117.52,6690.02 5117.52,6723.18 5126.9,6732.55 v2@5266.07,6732.55 ; 5156.07,3023.02 5222.77,3089.72 5222.77,3188.57 5220.01,3191.33 5220.01,3196.21 ; 5156.07,4103.02 5222.77,4169.72 5222.77,4268.57 5220.01,4271.33 5220.01,4276.21 ; 5156.07,5183.02 5222.77,5249.72 5222.77,5348.57 5220.01,5351.33 5220.01,5356.21 ; 5156.07,6263.02 5222.77,6329.72 5222.77,6428.57 5220.01,6431.33 5220.01,6436.21 ; 5165.44,3118.02 5185,3137.58 5185,3163.45 5193.77,3172.23 v4(5193.77,3176.56) ; 5165.44,4198.02 5185,4217.58 5185,4243.45 5193.77,4252.23 v4(5193.77,4256.56) ; 5165.44,5278.02 5185,5297.58 5185,5323.45 5193.77,5332.23 v4(5193.77,5336.56) ; 5165.44,6358.02 5185,6377.58 5185,6403.45 5193.77,6412.23 v4(5193.77,6416.56) ; v4@5194.17,3171.4 5194.17,3217.61 5194.29,3217.74 ; v4@5194.17,4251.4 5194.17,4297.61 5194.29,4297.74 ; v4@5194.17,5331.4 5194.17,5377.61 5194.29,5377.74 ; v4@5194.17,6411.4 5194.17,6457.61 5194.29,6457.74 ; 5245.48,3217.74 5245.48,3196.34 5246.07,3195.75 5246.07,3053.92 5247.83,3052.16 5247.83,3031.26 5256.07,3023.02 ; 5245.48,4297.74 5245.48,4276.34 5246.07,4275.75 5246.07,4133.92 5247.83,4132.16 5247.83,4111.26 5256.07,4103.02 ; 5245.48,5377.74 5245.48,5356.34 5246.07,5355.75 5246.07,5213.92 5247.83,5212.16 5247.83,5191.26 5256.07,5183.02 ; 5245.48,6457.74 5245.48,6436.34 5246.07,6435.75 5246.07,6293.92 5247.83,6292.16 5247.83,6271.26 5256.07,6263.02 ; v2(5266.07,3498.02) 5267.15,3498.02 5272.81,3492.36 5287.82,3492.36 5288.01,3492.55 5316.07,3492.55 ; v2(5266.07,4578.02) 5267.15,4578.02 5272.81,4572.36 5287.82,4572.36 5288.01,4572.55 5316.07,4572.55 ; v2(5266.07,5658.02) 5267.15,5658.02 5272.81,5652.36 5287.82,5652.36 5288.01,5652.55 5316.07,5652.55 ; v2(5266.07,6738.02) 5267.15,6738.02 5272.81,6732.36 5287.82,6732.36 5288.01,6732.55 5316.07,6732.55 ; 5271.07,3450.02 5271.19,3450.15 5271.19,3483.18 ; 5271.07,4530.02 5271.19,4530.15 5271.19,4563.18 ; 5271.07,5610.02 5271.19,5610.15 5271.19,5643.18 ; 5271.07,6690.02 5271.19,6690.15 5271.19,6723.18 ; 5296.66,3138.06 5296.66,3217.74 ; 5296.66,4218.06 5296.66,4297.74 ; 5296.66,5298.06 5296.66,5377.74 ; 5296.66,6378.06 5296.66,6457.74 ; 5322.25,3196.21 5322.25,3192.16 5348.86,3165.55 5423.38,3165.55 5431,3157.93 5431,3067.95 5407.59,3044.55 5377.59,3044.55 5356.07,3023.02 ; 5322.25,3471.43 5322.25,3450.02 5322.12,3450.15 5322.12,3486.5 5316.07,3492.55 ; 5322.25,4276.21 5322.25,4272.16 5348.86,4245.55 5423.38,4245.55 5431,4237.93 5431,4147.95 5407.59,4124.55 5377.59,4124.55 5356.07,4103.02 ; 5322.25,4551.43 5322.25,4530.02 5322.12,4530.15 5322.12,4566.5 5316.07,4572.55 ; 5322.25,5356.21 5322.25,5352.16 5348.86,5325.55 5423.38,5325.55 5431,5317.93 5431,5227.95 5407.59,5204.55 5377.59,5204.55 5356.07,5183.02 ; 5322.25,5631.43 5322.25,5610.02 5322.12,5610.15 5322.12,5646.5 5316.07,5652.55 ; 5322.25,6436.21 5322.25,6432.16 5348.86,6405.55 5423.38,6405.55 5431,6397.93 5431,6307.95 5407.59,6284.55 5377.59,6284.55 5356.07,6263.02 ; 5322.25,6711.43 5322.25,6690.02 5322.12,6690.15 5322.12,6726.5 5316.07,6732.55 ; 5373.43,3450.02 5373.43,3478.65 5359.53,3492.55 5316.07,3492.55 ; 5373.43,4530.02 5373.43,4558.65 5359.53,4572.55 5316.07,4572.55 ; 5373.43,5610.02 5373.43,5638.65 5359.53,5652.55 5316.07,5652.55 ; 5373.43,6690.02 5373.43,6718.65 5359.53,6732.55 5316.07,6732.55 ; 5857.52,3450.02 5857.52,3483.18 5866.9,3492.55 v2@6006.07,3492.55 ; 5857.52,4530.02 5857.52,4563.18 5866.9,4572.55 v2@6006.07,4572.55 ; 5857.52,5610.02 5857.52,5643.18 5866.9,5652.55 v2@6006.07,5652.55 ; 5857.52,6690.02 5857.52,6723.18 5866.9,6732.55 v2@6006.07,6732.55 ; 5896.07,3023.02 5962.77,3089.72 5962.77,3188.57 5960.01,3191.33 5960.01,3196.21 ; 5896.07,4103.02 5962.77,4169.72 5962.77,4268.57 5960.01,4271.33 5960.01,4276.21 ; 5896.07,5183.02 5962.77,5249.72 5962.77,5348.57 5960.01,5351.33 5960.01,5356.21 ; 5896.07,6263.02 5962.77,6329.72 5962.77,6428.57 5960.01,6431.33 5960.01,6436.21 ; 5905.44,3118.02 5925,3137.58 5925,3163.45 5933.77,3172.23 v4(5933.77,3176.56) ; 5905.44,4198.02 5925,4217.58 5925,4243.45 5933.77,4252.23 v4(5933.77,4256.56) ; 5905.44,5278.02 5925,5297.58 5925,5323.45 5933.77,5332.23 v4(5933.77,5336.56) ; 5905.44,6358.02 5925,6377.58 5925,6403.45 5933.77,6412.23 v4(5933.77,6416.56) ; v4@5934.17,3171.4 5934.17,3217.61 5934.29,3217.74 ; v4@5934.17,4251.4 5934.17,4297.61 5934.29,4297.74 ; v4@5934.17,5331.4 5934.17,5377.61 5934.29,5377.74 ; v4@5934.17,6411.4 5934.17,6457.61 5934.29,6457.74 ; 5985.48,3217.74 5985.48,3196.34 5986.07,3195.75 5986.07,3053.92 5987.83,3052.16 5987.83,3031.26 5996.07,3023.02 ; 5985.48,4297.74 5985.48,4276.34 5986.07,4275.75 5986.07,4133.92 5987.83,4132.16 5987.83,4111.26 5996.07,4103.02 ; 5985.48,5377.74 5985.48,5356.34 5986.07,5355.75 5986.07,5213.92 5987.83,5212.16 5987.83,5191.26 5996.07,5183.02 ; 5985.48,6457.74 5985.48,6436.34 5986.07,6435.75 5986.07,6293.92 5987.83,6292.16 5987.83,6271.26 5996.07,6263.02 ; v2(6006.07,3498.02) 6007.15,3498.02 6012.81,3492.36 6027.82,3492.36 6028.01,3492.55 6056.07,3492.55 ; v2(6006.07,4578.02) 6007.15,4578.02 6012.81,4572.36 6027.82,4572.36 6028.01,4572.55 6056.07,4572.55 ; v2(6006.07,5658.02) 6007.15,5658.02 6012.81,5652.36 6027.82,5652.36 6028.01,5652.55 6056.07,5652.55 ; v2(6006.07,6738.02) 6007.15,6738.02 6012.81,6732.36 6027.82,6732.36 6028.01,6732.55 6056.07,6732.55 ; 6011.07,3450.02 6011.19,3450.15 6011.19,3483.18 ; 6011.07,4530.02 6011.19,4530.15 6011.19,4563.18 ; 6011.07,5610.02 6011.19,5610.15 6011.19,5643.18 ; 6011.07,6690.02 6011.19,6690.15 6011.19,6723.18 ; 6036.66,3138.06 6036.66,3217.74 ; 6036.66,4218.06 6036.66,4297.74 ; 6036.66,5298.06 6036.66,5377.74 ; 6036.66,6378.06 6036.66,6457.74 ; 6062.25,3196.21 6062.25,3192.16 6088.86,3165.55 6163.38,3165.55 6171,3157.93 6171,3067.95 6147.59,3044.55 6117.59,3044.55 6096.07,3023.02 ; 6062.25,3471.43 6062.25,3450.02 6062.12,3450.15 6062.12,3486.5 6056.07,3492.55 ; 6062.25,4276.21 6062.25,4272.16 6088.86,4245.55 6163.38,4245.55 6171,4237.93 6171,4147.95 6147.59,4124.55 6117.59,4124.55 6096.07,4103.02 ; 6062.25,4551.43 6062.25,4530.02 6062.12,4530.15 6062.12,4566.5 6056.07,4572.55 ; 6062.25,5356.21 6062.25,5352.16 6088.86,5325.55 6163.38,5325.55 6171,5317.93 6171,5227.95 6147.59,5204.55 6117.59,5204.55 6096.07,5183.02 ; 6062.25,5631.43 6062.25,5610.02 6062.12,5610.15 6062.12,5646.5 6056.07,5652.55 ; 6062.25,6436.21 6062.25,6432.16 6088.86,6405.55 6163.38,6405.55 6171,6397.93 6171,6307.95 6147.59,6284.55 6117.59,6284.55 6096.07,6263.02 ; 6062.25,6711.43 6062.25,6690.02 6062.12,6690.15 6062.12,6726.5 6056.07,6732.55 ; 6113.43,3450.02 6113.43,3478.65 6099.53,3492.55 6056.07,3492.55 ; 6113.43,4530.02 6113.43,4558.65 6099.53,4572.55 6056.07,4572.55 ; 6113.43,5610.02 6113.43,5638.65 6099.53,5652.55 6056.07,5652.55 ; 6113.43,6690.02 6113.43,6718.65 6099.53,6732.55 6056.07,6732.55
